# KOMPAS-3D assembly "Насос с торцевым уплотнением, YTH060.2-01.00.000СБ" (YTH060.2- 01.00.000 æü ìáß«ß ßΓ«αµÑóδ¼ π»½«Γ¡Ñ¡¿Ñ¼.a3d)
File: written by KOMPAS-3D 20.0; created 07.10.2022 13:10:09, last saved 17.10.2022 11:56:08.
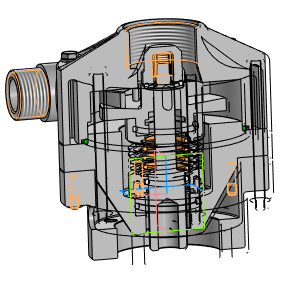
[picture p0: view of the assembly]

Document properties: Автор: Пользователь Windows; Полное имя файла: D:\информация пользователя\Desktop\ШОРОХ 2022\Насос ХИМия\YTH060.2 С торцевым уплотнением\YTH060.2 3D\YTH060.2- 01.00.000 СБ Насос сторцевым уплотнением.a3d

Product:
- Part/product: Насос с торцевым уплотнением  | designation YTH060.2-01.00.000СБ
    Масса: 1.71345
  - Component [detail]: Крышка корпуса  | designation YTH060.2-01.00.003  | pos. 3  | Материал: Полипропилен  ГОСТ 26996-86 (density 900 kg/m3); Масса: 0.255836; signatures: Разработал Шорохов Д.А.; Проверил Гуляев А.С.; Утвердил Басалов И.С.; source file: YTH060.2 - 01.00.003 Крышка корпуса .m3d
  - Component [detail]: Корпус верхний  | designation YTH060.2-01.00.001  | pos. 12  | Материал: Полипропилен 21015 ГОСТ 26996-86 (density 900 kg/m3); Масса: 0.422296; source file: YTH060.2 - 01.00.001 Корпус верхний .m3d
  - Component [detail]: Уплотнение прижимного кольца  | designation YTH060.2  | pos. 5  | Материал: Смесь резиновая В-14  ТУ 005.1166-87 (density 1280 kg/m3); Масса: 0.00160559; source file: YTH060.2 Уплотнение прижимного кольца .m3d
  - Component [detail]: Корпус основной  | designation YTH060.2-01.00.002  | pos. 16  | Материал: Полипропилен  ГОСТ 26996-86 (density 900 kg/m3); Масса: 0.346963; signatures: Разработал Шорохов Д.А.; Проверил Гуляев А.С.; Утвердил Басалов И.С.; source file: YTH060.2 - 01.00.002 Корпус основной .m3d
  - Component [detail]: Кольцо прижимное  | designation YTH060.2  | pos. 8  | Материал: Пресс-материал К-81-39  ТУ 6-05-1651-73 (density 1950 kg/m3); Масса: 0.0159475; source file: YTH060.2 Кольцо прижимное.m3d
  - Component [standard]: Кольцо 106-112-36-2-1 ГОСТ 9833-73  | pos. 40  | Материал: Смесь резиновая ИРП-1068 ТУ 38-1051082-86 (density 1280 kg/m3); Масса: 0.00344; Раздел спецификации: Стандартные изделия; Рассекать на разрезах: no; additional columns: 106-112-36-2-1
  - Component [assembly]: Вал крыльчатки в сборе  | designation YTH060.2-01.01.000СБ  | pos. 43  | Масса: 0.508863; signatures: Разработал Шорохов Д.А.; Проверил Гуляев А.С.; Утвердил Басалов И.С.; source file: YTH060.2-01.01.000 СБ Вал крыльчатки в сборе .a3d
  - Component [standard]: Шайба A.6.37 ГОСТ 11371-78  | qty 6  | pos. 76  | Материал: АД1 ГОСТ 4784-97 (density 1000 kg/m3); Масса: 0.001016; Раздел спецификации: Стандартные изделия; Рассекать на разрезах: no
  - Component [detail]: Болт М6х110 ГОСТ Р ИСО 4017-2013  | qty 6  | pos. 78  | Материал: Сталь 40  ГОСТ 1050-2013 (density 7850 kg/m3); Масса: 0.0249422; source file: Болт М6х100 ГОСТ Р ИСО 4017-2013.m3d
  - Component [standard]: Гайка шестигранная с фланцем ГОСТ Р ИСО 4161-М6  | qty 6  | pos. 79  | Материал: Не определено (density 1000 kg/m3); Масса: 0.000457929; Раздел спецификации: Стандартные изделия; Рассекать на разрезах: no; additional columns: ГОСТ Р ИСО 4161-2013; M6

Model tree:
1. Массив по концентрической сетке:4  (with: Операция без истории:1, Элемент выдавливания:3, Элемент выдавливания:2)  (6 pattern instances)
     Шаг 2 = 360

Referenced files in D:\информация пользователя\Desktop\ШОРОХ 2022\Насос ХИМия\YTH060.2 С торцевым уплотнением\YTH060.2 3D\: YTH060.2 - 01.00.003 Крышка корпуса .m3d, YTH060.2 Уплотнение прижимного кольца .m3d, YTH060.2 Кольцо прижимное.m3d, YTH060.2 - 01.00.001 Корпус верхний .m3d, YTH060.2 - 01.00.002 Корпус основной .m3d, YTH060.2-01.01.000 СБ Вал крыльчатки в сборе .a3d, Болт М6х110 ГОСТ Р ИСО 4017-2013.m3d, Болт М6х100 ГОСТ Р ИСО 4017-2013.m3d
Referenced files in C:\Program Files\ASCON\KOMPAS-3D v20\Libs\PARTLib\DATA\vault\Methods\Kompas\3D\: PLib_Ring_9833-73_712.m3d, PLib_Washer_1_712.m3d, PLib_Nut_ISO_1100.m3d
Referenced files in D:\информация пользователя\Desktop\ШОРОХ 2022\Насос ХИМия\YTH060.2 С торцевым уплотнением\3D  модель\YTH060.2 Насос сторцевым уплотнением\: Болт М6х100 ГОСТ Р ИСО 4017-2013.m3d
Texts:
  YTH060.2 - 01.00.003
  YTH060.2-01.00.003
  YTH060.2
  YTH060.2 - 01.00.001
  @100~)2xA3
  YTH060.2-01.00.001
  YTH060.2 - 01.00.002
  YTH060.2-01.00.002
  Кольцо резиновое уплотнительное
  YTH060.2 - 01.01.000
  YTH060.2-01.01.000 СБ
  YTH060.2 - 01.01.000     СБ
  Крепежное изделие ГОСТ
  Гайка шестигранная с фланцем
  ГОСТ Р ИСО
  Точка начала. Х
  Точка начала. Y
  Точка начала. Z
  YTH060.2 Кольцо прижимное
  YTH060.2-01.00.002 Корпус основной
  YTH060.2 Уплотнение прижимного кольца
  YTH060.2-01.00.001 Корпус верхний
  YTH060.2-01.00.003 Крышка корпуса
  YTH060.2-01.01.000 Вал крыльчатки в сборе
  Шайба A.6.37 ГОСТ 11371-78 (1)
  Болт М6х110 ГОСТ Р ИСО 4017-2013 (1)
  Гайка шестигранная с фланцем ГОСТ Р ИСО 4161-М6 (1)
  bcut1
  hole1
  hcut1
  r1pt
  hole2
  cut1
  cut2
  Болт М6х110 ГОСТ Р ИСО 4017-2013 (2)
  Шайба A.6.37 ГОСТ 11371-78 (2)
  Гайка шестигранная с фланцем ГОСТ Р ИСО 4161-М6 (2)
  Болт М6х110 ГОСТ Р ИСО 4017-2013 (3)
  Шайба A.6.37 ГОСТ 11371-78 (3)
  Гайка шестигранная с фланцем ГОСТ Р ИСО 4161-М6 (3)
  Болт М6х110 ГОСТ Р ИСО 4017-2013 (4)
  Шайба A.6.37 ГОСТ 11371-78 (4)
  Гайка шестигранная с фланцем ГОСТ Р ИСО 4161-М6 (4)
  Болт М6х110 ГОСТ Р ИСО 4017-2013 (5)
  Шайба A.6.37 ГОСТ 11371-78 (5)
  Гайка шестигранная с фланцем ГОСТ Р ИСО 4161-М6 (5)
  Болт М6х110 ГОСТ Р ИСО 4017-2013 (6)
  Шайба A.6.37 ГОСТ 11371-78 (6)
  Гайка шестигранная с фланцем ГОСТ Р ИСО 4161-М6 (6)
